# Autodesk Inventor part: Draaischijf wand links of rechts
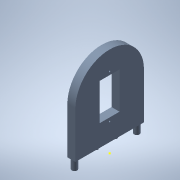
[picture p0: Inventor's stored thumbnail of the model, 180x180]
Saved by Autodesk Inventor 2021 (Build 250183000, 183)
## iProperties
Manager: Pierloot J.
Company: Emmaüs Bovenbouw Aalter
Created: 2015-08
Part Number: Draaischijf wand links of rechts
Material: S235
Catalog Web Link: http://emmausbovenbouw.op-weg.be/
Vendor: Emmaüsinstituut Bovenbouw Aalter
Document SubType Name: Modeling
Designer: Pierlootj
Engineer: Pierloot J.
Manufacturer: Standard
Standards Organization: Custom
Density: 7.86 g/cm^3
Appearance: Light Steel Blue
Title: Algemene titel
Subject: Specifieke titel
Author: Pierlootj
Keywords: Ruwe Ø xxxxx
Comments: Opmerking
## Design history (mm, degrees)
sketch "Sketch14"
  geometry: L1 (0, 0)-(-24.5, 0); L2 (-24.5, 0)-(24.5, 0); L3 (-24.5, 0)-(-24.5, -21.354); L4 (-24.5, 21.354)-(-19.5, 21.354); L5 (-19.5, 21.354)-(-19.5, -21.354); L6 (-19.5, -21.354)-(-24.5, -21.354); L7 (-24.5, -21.354)-(-24.5, 21.354); L8 (0, 27.067)-(0, -27.009); L9 (19.5, -21.354)-(24.5, -21.354); L10 (19.5, 21.354)-(19.5, -21.354); L11 (24.5, -21.354)-(24.5, 21.354); L12 (24.5, 21.354)-(19.5, 21.354); A1 r 32.5 centre (0, 0) between (-24.5, -21.354) and (-24.5, 21.354)
  constraints: 24 end point, 4 symmetric about line, 2 horizontal, 2 parallel, 2 point on circle, 2 vertical, 1 centre point, 1 coincident, 1 perpendicular, 1 point on line
  dimensions: "d105" = 24.5 distance of L1.start L1.end; "d106" = 49 distance of L1.end L2.end; "d107" = 65 diameter of A1; "d108" = 5 distance of L5.end L6.end
extrude "Extrusion12" new body sketch "Sketch14" distance "d109" = 6; taper "d110" = 0 deg
sketch "Sketch15"
  geometry: L1 (0, 0)-(-24.5, 0); L2 (-24.5, 0)-(24.5, 0); L3 (-24.5, -21.354)-(-24.5, 21.354); L4 (0, 27.067)-(0, -27.009); L5 (19.5, -21.354)-(24.5, -21.354); L6 (19.5, 21.354)-(19.5, -21.354); L7 (24.5, -21.354)-(24.5, 21.354); L8 (24.5, 21.354)-(19.5, 21.354); L9 (-24.5, -21.354)-(-19.5, -21.354); L10 (-19.5, -21.354)-(-19.5, 21.354); L11 (-19.5, 21.354)-(-24.5, 21.354); L12 (-24.5, 21.354)-(-24.5, -21.354); 1 further point
  constraints: 24 end point, 2 horizontal, 2 parallel, 2 symmetric about line, 1 perpendicular, 1 point on line, 1 vertical
  dimensions: "d111" = 24.5 distance of L1.start L1.end; "d112" = 49 distance of L1.end L2.end; "d131" = 5 distance of L11.end L10.end
extrude "Extrusion13" join sketch "Sketch15" distance "d115" = 50; taper "d116" = 0 deg
fillet "Fillet5" dims "d117" = 21.3
sketch "Sketch17"
  geometry: L1 (0, 42.708)-(0, 0) reference; L2 (0, 21.354)-(-30, 21.354); L3 (-30, 21.354)-(-13.35, 21.354); L4 (-13.35, 21.354)-(-13.35, 27.509); L5 (-13.35, 27.509)-(-36.15, 27.509); L6 (-36.15, 27.509)-(-36.15, 15.209); L7 (-36.15, 15.209)-(-13.35, 15.209); L8 (-13.35, 15.209)-(-13.35, 27.509); 2 further points
  constraints: 14 end point, 2 horizontal, 2 parallel, 2 perpendicular, 1 midpoint, 1 point on line
  dimensions: "d122" = 30 distance of L2.start L2.end; "d190" = 16.65 distance of L2.end L3.end; "d191" = 22.8 distance of L7.end L6.end; "d192" = 12.3 distance of L6.end L5.end
sketch "Sketch19"
  geometry: L1 (0, 0)-(0, 42.708) reference; L2 (0, 21.354)-(30, 21.354); C1 r 7.65 at (30, 21.354); 1 further point
  constraints: 2 end point, 1 centre point, 1 coincident, 1 horizontal, 1 midpoint
  dimensions: "d132" = 30 distance of L2.start L2.end; "d184" = 15.3 diameter of C1
fillet "Fillet6" dims "d136" = 21.3
sketch "Sketch20"
  geometry: C1 r 13 at (30, 21.354) reference; C2 r 6.5 at (30, 21.354); C3 r 7.75 at (30, 21.354); 1 further point
  constraints: 2 centre point, 2 coincident
  dimensions: "d137" = 13 diameter of C2; "d138" = 15.5 diameter of C3
extrude "Extrusion18" join sketch "Sketch20" distance "d139" = 1; taper "d140" = 0 deg
sketch "Sketch21"
  geometry: C1 r 2.5 at (0, 0) reference; C2 r 26.15 at (0, 0); C3 r 17.35 at (0, 0); 1 further point
  constraints: 2 centre point, 2 coincident
  dimensions: "d144" = 52.3 diameter of C2; "d145" = 34.7 diameter of C3
extrude "Extrusion19" cut sketch "Sketch21" distance "d146" = 4.3; taper "d147" = 0 deg
sketch "Sketch22"
  geometry: 1 further point
sketch "Sketch23"
  geometry: L1 (-35.75, 27.504)-(-35.75, 15.204) reference; L2 (-35.75, 21.354)-(-38.25, 21.354); L3 (-13.25, 27.504)-(-13.25, 15.204) reference; L4 (-13.25, 21.354)-(-11.25, 21.354); C1 r 0.5 at (-38.25, 21.354); C2 r 0.5 at (-11.25, 21.354); 1 further point
  constraints: 4 end point, 2 centre point, 2 coincident, 2 horizontal, 2 midpoint
  dimensions: "d150" = 2.5 distance of L2.start L2.end; "d151" = 1 diameter of C1; "d152" = 2 distance of L4.start L4.end; "d153" = 1 diameter of C2
extrude "Extrusion21" cut sketch "Sketch23" stored distance "d154" = 4.3; taper "d155" = 0 deg
extrude "Extrusion23" cut sketch "Sketch19" stored distance "d185" = 10; taper "d186" = 0 deg
chamfer "Chamfer2" distance "d187" = 1; stored, may be unused: second distance "d188" = 2, angle "d189" = 45 deg
extrude "Extrusion24" cut sketch "Sketch17" stored distance "d193" = 10; taper "d194" = 0 deg
sketch "Sketch25"
  geometry: L1 (2.197, 15.216)-(2.899, 1.91); L2 (-2.197, 15.216)-(-2.894, 2.01); L3 (2.899, 1.91)-(3, 0); L4 (-2.894, 2.01)-(-3, 0); L5 (-13.698, 0)-(13.244, 0); L6 (2.197, -15.216)-(2.899, -1.91); L7 (-2.197, -15.216)-(-2.894, -2.01); L8 (-2.894, -2.01)-(-3, 0); L9 (2.899, -1.91)-(3, 0); L10 (7.35, 1.1)-(3.327, 1.1); L11 (-3.454, 1.1)-(-7.35, 1.1); L12 (7.35, -1.1)-(3.207, -1.1); L13 (-3.263, -1.238)-(-7.387, -1.099); L14 (-3.876, 2.377)-(-3.196, 15.269); L15 (3.196, 15.269)-(3.884, 2.229); L16 (3.959, 2.1)-(7.35, 2.1); L17 (7.35, -2.1)-(3.918, -2.1); L18 (3.887, -2.168)-(3.196, -15.269); L19 (-3.196, -15.269)-(-3.879, -2.313); L20 (-3.932, -2.216)-(-7.421, -2.099); L21 (-7.35, 2.1)-(-4.061, 2.1); A1 r 2.2 centre (0, 15.1) between (2.197, 15.216) and (-2.197, 15.216); A2 r 2.2 centre (0, -15.1) between (-2.197, -15.216) and (2.197, -15.216); A3 r 1.1 centre (7.35, 0) between (7.35, -1.1) and (7.35, 1.1); A4 r 1.1 centre (-7.35, 0) between (-7.35, 1.1) and (-7.387, -1.099); A5 r 3.537 centre (-0.229, -0.259) between (2.899, -1.91) and (3.207, -1.1); A6 r 3.806 centre (-0.229, -0.259) between (3.327, 1.1) and (2.899, 1.91); A7 r 3.5 centre (-0.229, -0.259) between (-2.894, 2.01) and (-3.454, 1.1); A8 r 3.189 centre (-0.229, -0.259) between (-3.263, -1.238) and (-2.894, -2.01); A9 r 4.806 centre (-0.229, -0.259) between (3.959, 2.1) and (3.884, 2.229); A10 r 2.1 centre (7.35, 0) between (7.35, -2.1) and (7.35, 2.1); A11 r 4.537 centre (-0.229, -0.259) between (3.887, -2.168) and (3.918, -2.1); A12 r 4.189 centre (-0.229, -0.259) between (-3.932, -2.216) and (-3.879, -2.313); A13 r 2.1 centre (-7.35, 0) between (-7.35, 2.1) and (-7.421, -2.099); A14 r 4.5 centre (-0.229, -0.259) between (-3.876, 2.377) and (-4.061, 2.1); A15 r 17.35 centre (0, 0) between (2.433, 17.179) and (-2.433, 17.179) reference; A16 r 17.35 centre (0, 0) between (2.433, 17.179) and (-2.433, 17.179); A17 r 17.35 centre (0, 0) between (-2.433, -17.179) and (2.433, -17.179); A18 r 3.2 centre (0, 15.1) between (3.196, 15.269) and (2.433, 17.179); A19 r 3.2 centre (0, 15.1) between (-2.433, 17.179) and (-3.196, 15.269); A20 r 3.2 centre (0, -15.1) between (-3.196, -15.269) and (-2.433, -17.179); A21 r 3.2 centre (0, -15.1) between (2.433, -17.179) and (3.196, -15.269); 3 further points
  constraints: 44 point on circle, 42 end point, 20 centre point, 6 tangent, 5 symmetric about line, 3 point on line, 2 coincident, 2 horizontal alignment, 2 parallel, 1 horizontal, 1 vertical alignment, 12 other
  dimensions: "d197" = 3 distance of L3.end point (0, 0); "d198" = 3 distance of L4.end point (0, 0); "d199" = 15.1 distance of A1.centre point (0, 0); "d200" = 2.2 radius of A1; "d201" = 2.2 diameter of A3; "d202" = 2.2 diameter of A4; "d203" = 14.7 distance of A4.centre A3.centre; "d204" = 7.35 distance of point (0, 0) A3.centre (derived); "d205" = 1 distance between parallel lines of L2 L14
extrude "Extrusion26" join sketch "Sketch25" distance "d206" = 2.6; taper "d207" = 0 deg
chamfer "Chamfer3" distance "d208" = 1; stored, may be unused: second distance "d209" = 2, angle "d210" = 45 deg
sketch "Sketch26"
  geometry: L1 (-4.67, 16.71)-(-4.498, 15.719); L2 (4.609, 15.687)-(5.257, 16.534); L3 (-13.838, 0)-(14.49, 0); L4 (4.609, -15.687)-(5.257, -16.534); L5 (-4.67, -16.71)-(-4.498, -15.719); A1 r 17.35 centre (0, 0) between (3.779, -16.934) and (3.779, 16.934) reference; A2 r 17.35 centre (0, 0) between (-3.779, 16.934) and (-3.779, -16.934) reference; A3 r 17.35 centre (0, 0) between (5.257, 16.534) and (-4.67, 16.71); A4 r 16.35 centre (0, 0) between (4.609, 15.687) and (-4.498, 15.719); A5 r 17.35 centre (0, 0) between (-4.67, -16.71) and (5.257, -16.534); A6 r 16.35 centre (0, 0) between (-4.498, -15.719) and (4.609, -15.687); 7 further points
  constraints: 10 end point, 10 point on circle, 4 centre point, 4 symmetric about line, 2 coincident, 1 horizontal, 2 other
  dimensions: "d211" = 16.35 radius of A4
extrude "Extrusion27" cut sketch "Sketch26" distance "d212" = 2.6; taper "d213" = 0 deg
sketch "Sketch29"
  geometry: L1 (24.5, 21.354)-(24.5, -21.354) reference; L2 (24.5, 0)-(26, 0); L3 (26, 0)-(26, 4.25); L4 (26, 4.25)-(29.5, 4.25); L5 (29.5, 4.25)-(29.5, -4.25); L6 (29.5, -4.25)-(26, -4.25); L7 (26, -4.25)-(26, 4.25); 2 further points
  constraints: 12 end point, 2 horizontal, 2 parallel, 2 perpendicular, 1 midpoint
  dimensions: "d226" = 1.5 distance of L2.start L2.end; "d227" = 4.25 distance of L2.end L3.end; "d228" = 3.5 distance of L5.end L6.end; "d229" = 8.5 distance of L4.end L5.end
extrude "Extrusion30" cut sketch "Sketch29" extent not by distance; stored distance "d230" = 0; taper "d231" = 0 deg
sketch "Sketch30"
  geometry: C1 r 64.799 at (0, 0); 1 further point
  constraints: 1 centre point, 1 coincident
extrude "Extrusion31" cut sketch "Sketch30" distance "d232" = 8.6; taper "d233" = 0 deg
sketch "Sketch32"
  geometry: L1 (-24.5, -21.354)-(-19.5, -17.423); L2 (-19.5, -17.423)-(-22, -19.389); L3 (0, 0)-(-22.867, 0); L4 (0, -23.308)-(0, 14.95); C1 r 1.65 at (-22, -19.389); C2 r 1.65 at (-22, 19.389); C3 r 1.65 at (22, -19.389); C4 r 1.65 at (22, 19.389); 1 further point
  constraints: 8 end point, 4 centre point, 3 symmetric about line, 1 coincident, 1 horizontal, 1 midpoint, 1 vertical, 3 other
  dimensions: "d236" = 3.3 diameter of C1
extrude "Extrusion33" join sketch "Sketch32" distance "d237" = 6; taper "d238" = 0 deg
sketch "Sketch33"
  geometry: L1 (19.5, -21.354)-(24.5, -21.354) reference; L2 (24.5, -21.354)-(24.5, 0); L3 (19.5, 21.354)-(24.5, 21.354) reference; L4 (24.5, 0)-(22, 0); L5 (19.5, -0.054)-(19.5, 0.054) reference; L6 (22, 0)-(22, -6); L7 (22, -6)-(22, 6); L8 (0, 0)-(0, -14.735); C1 r 1.25 at (22, -6); C2 r 1.25 at (22, 6); C3 r 1.25 at (-22, -6); C4 r 1.25 at (-22, 6)
  constraints: 10 end point, 4 centre point, 2 coincident, 2 perpendicular, 2 symmetric about line, 2 vertical, 1 point on line, 2 other
  dimensions: "d239" = 2.5 distance of L2.end L4.end; "d240" = 6 distance of L4.end L6.end; "d241" = 12 distance of L6.end L7.end; "d242" = 2.5 diameter of C1; "d243" = 2.5 diameter of C2
extrude "Extrusion34" join sketch "Sketch33" distance "d244" = 1.7; taper "d245" = 0 deg
sketch "Sketch34"
  geometry: C1 r 45.447 at (-23.809, 21.354); 1 further point
  constraints: 1 centre point
extrude "Extrusion35" cut sketch "Sketch34" distance "d246" = 10; taper "d247" = 0 deg
body "Solid6"
